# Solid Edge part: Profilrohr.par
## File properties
Username: bmolnar
Dokumentum tartalom típus: 0
Author: bmolnar
Last saved by: bmolnar
Revision: 90
Sűrűség: 0,000 kg/m^3
Pontosság: 0,990
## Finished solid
Body 1: solid body, 115 faces, 338 edges, 224 vertices.
  Faces by surface: cylinder 59, plane 56
  Edges by curve: line 220, circle 118
Bounding box of the edges (mm): 77.000 x 77.000 x 146.500, from (-38.5, -38.5, 0) to (38.5, 38.5, 146.5).
Cylindrical faces by radius (mm): R0.15 x24, R0.25 x24, R1 x4, R12 x4, R13.5 x2, R31.5 x1
Planar faces by outward normal: +x 13, +y 14, +z 1, -x 13, -y 14, -z 1
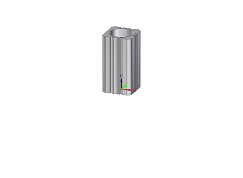
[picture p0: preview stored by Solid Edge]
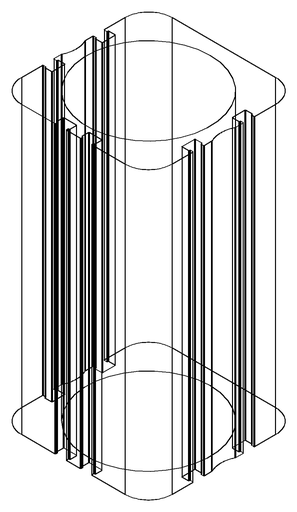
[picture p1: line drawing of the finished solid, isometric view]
